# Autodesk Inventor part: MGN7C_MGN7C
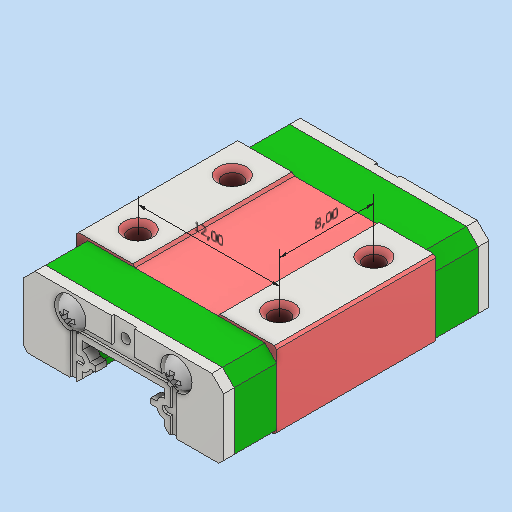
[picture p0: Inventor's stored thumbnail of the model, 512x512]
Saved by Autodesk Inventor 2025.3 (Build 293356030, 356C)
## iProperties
Created: 2019-04
Part Number: MGN7C_MGN7C
Material: Generico
Document SubType Name: Modeling
Designer: R5800u
Density: 1 g/cm^3
Appearance: Default
Author: R5800u
Revision Number: ANY
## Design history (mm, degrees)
node "Annotazioni"
  node "Quota lineare 1" dims "d2" = 8 (derived)
  node "Quota lineare 2" dims "d5" = 12 (derived)
feature "Sculpt1"
feature "Chamfer6" [Sculpt]
feature "Extrude10[1]" [Sculpt]
feature "Extrude10[2]" [Sculpt]
feature "Extrude7" [Sculpt]
feature "Mirror1[2]" [Sculpt]
feature "Mirror1[3]" [Sculpt]
feature "Mirror1[4]" [Sculpt]
feature "Mirror1[5]" [Sculpt]
node "Solido1"
node "Solido2"
node "Solido3"
node "Solido4"
node "Solido5"
node "Solido6"
node "Solido7"
node "Solido8"
node "Solido9"
other parameters: "d0" = -1.05005 (derived), "d1" = -0.79308 (derived), "d3" = -0.75598 (derived), "d4" = -0.6522 (derived)
